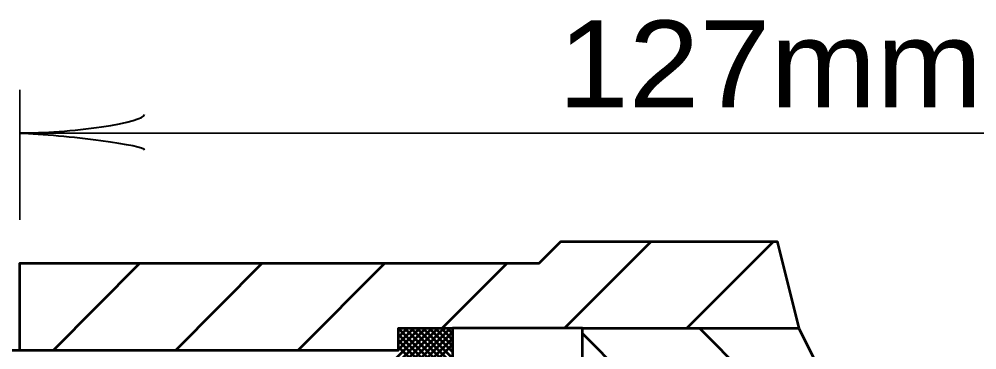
# Model space of a CAD drawing. Extents: x -32 to 824, y -6 to 538.
# Drawn here: x 367.71 to 394.27, y 433 to 442.15 of the extents above; entities that cross this region are included whole.
import ezdxf

# ---------------------------------------------------------------- set-up
doc = ezdxf.new("R2010")
doc.units = 0
doc.header["$LTSCALE"] = 1.1
doc.layers.add('1', color=7, linetype='Continuous', lineweight=53)

msp = doc.modelspace()

# ---------------------------------------------------------------- linework, layer by layer
at = {"layer": '1', "lineweight": 35}
for p, q in [((367.736, 436.596), (367.736, 440.196)), ((367.736, 438.996), (408.517, 438.996))]:
    msp.add_line(p, q, dxfattribs=at)
at = {"layer": '1'}
for p, q in [((382.84, 433.596), (385.24, 435.996)), ((386.234, 433.596), (388.634, 435.996)), ((368.664, 432.996), (371.064, 435.396)), ((372.058, 432.996), (374.458, 435.396)), ((375.452, 432.996), (377.852, 435.396)), ((379.446, 433.596), (381.246, 435.396)), ((376.745, 431.346), (378.995, 433.596)), ((376.915, 431.346), (379.165, 433.596)), ((377.084, 431.346), (379.334, 433.596)), ((377.254, 431.346), (379.504, 433.596)), ((377.424, 431.346), (379.674, 433.596)), ((377.594, 431.346), (379.736, 433.489)), ((378.236, 433.516), (378.316, 433.596)), ((378.236, 433.347), (378.486, 433.596)), ((378.236, 433.177), (378.656, 433.596)), ((378.236, 433.007), (378.825, 433.596)), ((379.736, 432.094), (378.236, 433.594)), ((379.736, 431.925), (378.236, 433.425)), ((379.736, 432.264), (378.404, 433.596)), ((379.736, 432.434), (378.574, 433.596)), ((379.736, 432.603), (378.744, 433.596)), ((379.736, 432.773), (378.913, 433.596)), ((379.736, 432.943), (379.083, 433.596)), ((379.736, 433.112), (379.253, 433.596)), ((379.736, 433.282), (379.422, 433.596)), ((379.736, 433.452), (379.592, 433.596)), ((383.336, 433.596), (379.736, 433.596)), ((389.789, 426.996), (383.336, 433.449)), ((390.536, 429.643), (386.583, 433.596)), ((377.636, 431.219), (379.736, 433.319)), ((379.736, 431.755), (378.236, 433.255)), ((377.636, 431.05), (379.736, 433.15)), ((379.736, 431.585), (378.236, 433.085))]:
    msp.add_line(p, q, dxfattribs=at)
for points in [[(367.736, 432.996), (367.736, 435.396), (382.136, 435.396), (382.736, 435.996), (388.736, 435.996), (389.336, 433.596)], [(383.336, 423.096), (383.336, 427.896), (383.336, 433.596), (389.336, 433.596), (390.536, 431.196), (390.536, 426.996), (388.736, 426.996), (387.536, 426.996)]]:
    msp.add_lwpolyline(points, dxfattribs=at)
msp.add_lwpolyline([(354.836, 430.146), (354.836, 431.646), (354.836, 432.996), (367.736, 432.996), (378.236, 432.996), (378.236, 433.596), (379.736, 433.596), (379.736, 417.396), (378.236, 417.396), (378.236, 417.996), (367.736, 417.996), (354.836, 417.996), (354.836, 419.346), (354.836, 420.846), (354.836, 422.196), (367.736, 422.196), (377.636, 422.196), (377.636, 428.796), (367.736, 428.796), (354.836, 428.796)], close=True, dxfattribs=at)
at = {"layer": '1', "lineweight": 40}
for centre, major_axis, ratio, start_param, end_param in [((369.046, 439.328), (-2.143, -0.187), 0.122415, 0.896353, 3.141593), ((369.046, 439.328), (-2.143, -0.187), 0.122415, 0.896353, 3.141593), ((369.081, 438.742), (-2.108, 0.211), 0.07063, 3.140715, 5.41811), ((369.081, 438.742), (-2.108, 0.211), 0.07063, 3.140715, 5.41811)]:
    msp.add_ellipse(centre, major_axis=major_axis, ratio=ratio, start_param=start_param, end_param=end_param, dxfattribs=at)

# ---------------------------------------------------------------- texts
at = {"layer": '1', "width": 1.1}
msp.add_text('127mm', height=2.4, dxfattribs=at).set_placement((382.655, 439.717))

doc.saveas('drawing.dxf')
